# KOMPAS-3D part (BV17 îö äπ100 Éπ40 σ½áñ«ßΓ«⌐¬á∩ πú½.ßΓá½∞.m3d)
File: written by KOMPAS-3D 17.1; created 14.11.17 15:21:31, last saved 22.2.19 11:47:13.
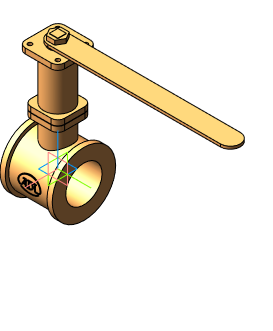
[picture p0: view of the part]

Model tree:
1. Операция без истории:1  (labels: Сталь 20  ГОСТ 1050-2013)

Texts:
  Линейный размер с обрывом
  Толщина листового тела
  Глубина освобождения сгиба
  Ширина освобождения сгиба
  BV17 МФ Ду15 Ру40 хладостойкая угл.сталь
  BV17 МФ Ду20 Ру40 хладостойкая угл.сталь
  BV17 МФ Ду25 Ру40 хладостойкая угл.сталь
  BV17 МФ Ду32 Ру40 хладостойкая угл.сталь
  BV17 МФ Ду40 Ру40 хладостойкая угл.сталь
  BV17 МФ Ду50 Ру40 хладостойкая угл.сталь
  BV17 МФ Ду65 Ру40 хладостойкая угл.сталь
  BV17 МФ Ду80 Ру40 хладостойкая угл.сталь
  BV17 МФ Ду100 Ру40 хладостойкая угл.сталь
